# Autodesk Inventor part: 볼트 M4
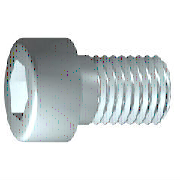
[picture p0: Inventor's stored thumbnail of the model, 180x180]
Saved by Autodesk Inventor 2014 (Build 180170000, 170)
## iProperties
IsCustomPart: 1
Created: 2012-02
Part Number: 볼트 M4
Material: 강철, 연강
Description: 6각머리 태핑 나사
Document SubType Name: Modeling
Standard: KS B 1003
Designer: mduedu
Standards Organization: KS
Language: ko-KR
Size Designation: M 4 x 10
Categories: <MemberInstance><Categories><Category DisplayName="조임쇠" InternalName="e4da775c-781d-43d5-af7c-5136215cf5a6" Mnemonic="FSTN"><Category DisplayName="볼트" InternalN
Density: 1 g/cm^3
Appearance: Steel
Author: mduedu
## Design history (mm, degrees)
sketch "스케치1"
  geometry: L1 (-1, 0)-(10, 0); L2 (10, 0)-(10, 2); L3 (10, 2)-(1.75, 2); L4 (1.75, 2)-(1.32, 2); L5 (1.32, 2)-(0, 2); L6 (0, 2)-(0, 3.5); L7 (0, 3.5)-(-4, 3.5); L8 (-4, 3.5)-(-4, 1.732); L9 (-4, 1.732)-(-2, 1.732); L10 (-2, 1.732)-(-1, 0); L11 (-6.8, 0)-(12.8, 0) reference; L12 (0, -0.7)-(0, 4.2) reference; L13 (1.75, 2)-(0, 2)
  constraints: 22 end point, 6 parallel, 2 collinear, 2 perpendicular, 1 horizontal, 1 point on line
  dimensions: "d1" = 8.25 distance from line of L3.end L2 (= GEL); "d2" = 0.42952 distance of L4.end L3.end (computed from GAL); "d3" = 4 distance between parallel lines of L8 L6 (= KOH); "d4" = 2 distance of L8.end L9.end (= INTI); "d5" = 60 deg angle of L10 L1; "d6" = 4 diameter of L3 L1 (= GD); "d7" = 4 diameter of L5 L1 (= BDM); "d8" = 3.4641 diameter of L9 L1 (= 1.1547 x SW); "d9" = 7 diameter of L7 L1 (= KOD); "d26" = 10 distance between parallel lines of L12 L2 (= NLG)
revolve "본체" sketch "스케치1" stored, may be unused: angle "d10" = 90 deg
sketch "스케치2"
  geometry: L1 (0, -4.9)-(0, 4.9) reference; L2 (-4.9, 0)-(4.9, 0) reference; L3 (1.732, 0)-(0.866, -1.5); L4 (0.866, -1.5)-(-0.866, -1.5); L5 (-0.866, -1.5)-(-1.732, 0); L6 (-1.732, 0)-(-0.866, 1.5); L7 (-0.866, 1.5)-(0.866, 1.5); L8 (0.866, 1.5)-(1.732, 0); 2 further points
  constraints: 12 end point, 1 coincident, 1 horizontal alignment, 1 point on line, 12 other
extrude "슬롯" join sketch "스케치2" stored distance "d11" = 10; taper "d12" = 0 deg
workplane "Work Plane1"
fillet "Fillet2" dims "d30" = 0.1 (= R)
body "Solid1"
fillet "모깎기1" dims "d17" = 0.4 (= RR)
feature "스레드" dims "d13" = 8.25 (= GEL), "d14" = 0
chamfer "모따기1" distance "d15" = 0.42941 (= -0.5 x SPD + 0.5 x GD); stored, may be unused: second distance "d16" = 0.42941 (= GUL), angle "d27" = 45 deg
other parameters: "GD" = 4 (= NND) [user parameter; used in 2 equation terms], "NLG" = 10 [user parameter; used in 1 equation term], "GEL" = 8.25 [user parameter; used in 2 equation terms], "KOD" = 7 [user parameter; used in 1 equation term], "KOH" = 4 [user parameter; used in 1 equation term], "INTI" = 2 [user parameter; used in 1 equation term], "GAL" = 0.42941 (= 0.61345 x PTC) [user parameter; used in 1 equation term], "GUL" = 0.42941 (= 0.61345 x PTC) [user parameter; used in 1 equation term], "BDM" = 4 (= NND) [user parameter; used in 1 equation term], "SW" = 3 [user parameter; used in 2 equation terms], "RR" = 0.4 [user parameter; used in 1 equation term], "SPD" = 3.14117 (= NND - 1.2269 x PTC) [user parameter; used in 1 equation term], "d19" = 0, "d28" = 0, "d29" = 0, "R" = 0.1 [user parameter; used in 1 equation term], "PHH" = 0.2 [user parameter], "GD1" = 3.14117 (= THREADDIA - 1.2269 x PTC) [user parameter], "THREADDIA" = 4 [user parameter; used in 1 equation term], "FAWI" = 45 deg [user parameter], "TPU" = 14.28571 (computed from PTC) [user parameter], "PTC" = 0.7 [user parameter; used in 5 equation terms], "NND" = 4 [user parameter; used in 3 equation terms], "TOA" = 30 deg [user parameter], "E0" = 3.465 (= 1.155 x SW) [user parameter]
